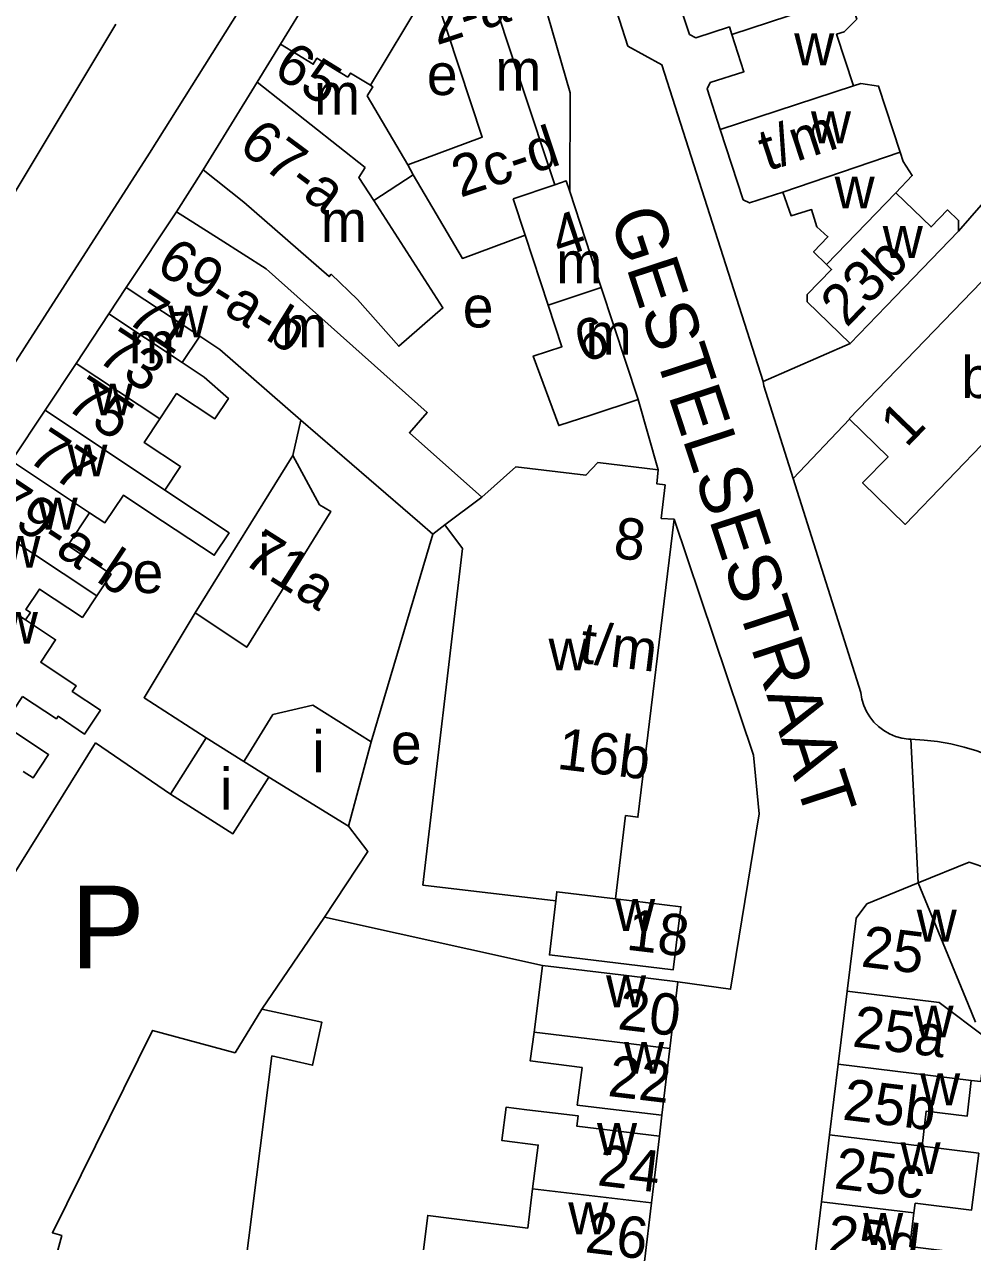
# Model space of a CAD drawing. Extents: x 159700 to 161346, y 381730 to 382922.
# Drawn here: x 160837.1 to 160928.7, y 382582.1 to 382699.7 of the extents above; entities that cross this region are included whole.
import ezdxf

# ---------------------------------------------------------------- set-up
doc = ezdxf.new("R2010")
doc.units = 0
for name, color, linetype in [('BLT_Basislijn', 7, 'Continuous'), ('BLT_Bebouwing', 7, 'Continuous'), ('BLT_Centroide', 7, 'Continuous'), ('BLT_Huisnummer', 7, 'Continuous'), ('BLT_Huisnummer_ tussenligend', 7, 'Continuous'), ('BLT_Huisnummer_reeks', 7, 'Continuous'), ('BLT_Onderdoorgang_en_onderverdeling', 7, 'Continuous'), ('BLT_Onderverdeling_panden', 7, 'Continuous'), ('BLT_Straatnaam', 7, 'Continuous'), ('BLT_Tekst_parkeren', 7, 'Continuous'), ('BLT_Vlakafsluiter', 7, 'Continuous')]:
    doc.layers.add(name, color=color, linetype=linetype)

msp = doc.modelspace()

# ---------------------------------------------------------------- linework, layer by layer
at = {"layer": 'BLT_Basislijn'}
for p, q in [((160854.35, 382685.66), (160851.76, 382681.61)), ((160916.88, 382668.89), (160908.48, 382665.22)), ((160908.48, 382665.22), (160908.53, 382664.81)), ((160908.53, 382664.81), (160911.37, 382655.83)), ((160863.02, 382658.08), (160863.78, 382661.49)), ((160916.8, 382661.59), (160911.37, 382655.83)), ((160911.37, 382655.83), (160917.91, 382635.15)), ((160870.58, 382630.4), (160876.54, 382650.47)), ((160832.19, 382611.45), (160843.92, 382630.3)), ((160843.92, 382630.3), (160851.18, 382625.33)), ((160858.26, 382628.5), (160858.48, 382628.86)), ((160866.07, 382613.44), (160860.02, 382604.55)), ((160887.13, 382608.77), (160866.07, 382613.44)), ((160898.44, 382592.3), (160898.68, 382594.31))]:
    msp.add_line(p, q, dxfattribs=at)
for points in [[(160908.48, 382665.22), (160898.67, 382695.83), (160895.37, 382697.63), (160884.95, 382730.18)], [(160869.96, 382717.52), (160865.52, 382713.53), (160860.57, 382705.45), (160849.16, 382687.27)], [(160885.08, 382709.55), (160889.8, 382693.12), (160889.77, 382683.58)], [(160849.16, 382687.27), (160822.99, 382646.61), (160791.29, 382599.29)], [(160937.77, 382688.16), (160933.93, 382687.28), (160927.35, 382679.74)], [(160896.37, 382663.48), (160898.33, 382656.68)], [(160899.85, 382651.91), (160907.53, 382629.1), (160908.07, 382623.44), (160905.31, 382606.48), (160900.23, 382607.21)], [(160917.91, 382635.15), (160918.01, 382634.53), (160918.19, 382633.92), (160918.45, 382633.34), (160918.78, 382632.8), (160919.17, 382632.3), (160919.62, 382631.86), (160920.13, 382631.48), (160920.68, 382631.16), (160921.26, 382630.92), (160921.88, 382630.74), (160922.5, 382630.65), (160922.73, 382630.64)], [(160922.73, 382630.64), (160924.03, 382630.57), (160925.33, 382630.42), (160926.61, 382630.2), (160927.88, 382629.89), (160929.13, 382629.51), (160930.35, 382629.05), (160931.54, 382628.51), (160932.7, 382627.91), (160933.82, 382627.24), (160934.89, 382626.49), (160935.92, 382625.69), (160936.89, 382624.82), (160937.81, 382623.89), (160938.67, 382622.91), (160939.06, 382622.43)], [(160866.07, 382613.44), (160870.25, 382619.8), (160868.39, 382622.25)]]:
    msp.add_lwpolyline(points, dxfattribs=at)
at = {"layer": 'BLT_Bebouwing'}
for p, q in [((160867.49, 382707.07), (160861.82, 382697.83)), ((160870.51, 382693.84), (160875.99, 382703.02)), ((160861.82, 382697.83), (160859.55, 382694.14)), ((160859.55, 382694.14), (160854.35, 382685.66)), ((160874.11, 382686.15), (160870.2, 382692.84)), ((160870.83, 382682.7), (160874.64, 382685.19)), ((160889.77, 382683.58), (160892.82, 382674.3)), ((160851.76, 382681.61), (160846.91, 382674.29)), ((160916.79, 382661.6), (160930.49, 382675.81)), ((160846.91, 382674.29), (160845.22, 382671.75)), ((160896.37, 382663.48), (160892.82, 382674.3)), ((160845.22, 382671.75), (160842.06, 382666.97)), ((160854, 382669.6), (160852.31, 382667.05)), ((160842.06, 382666.97), (160839.07, 382662.45)), ((160839.07, 382662.45), (160835.81, 382657.54)), ((160875.29, 382651.56), (160863.78, 382661.49)), ((160916.8, 382661.59), (160916.79, 382661.6)), ((160853.56, 382642.87), (160863.02, 382658.08)), ((160854.64, 382630.79), (160851.18, 382625.34)), ((160854.64, 382630.79), (160858.26, 382628.5)), ((160868.39, 382622.25), (160870.58, 382630.4)), ((160868.39, 382622.25), (160860.7, 382626.99)), ((160875.57, 382616.54), (160888.41, 382615.03)), ((160900.23, 382607.21), (160899.46, 382600.76)), ((160915.73, 382599.25), (160916.59, 382606.29)), ((160899.46, 382600.76), (160898.68, 382594.31)), ((160860.97, 382600.04), (160854.79, 382550.82)), ((160914.89, 382592.4), (160915.73, 382599.25)), ((160898.44, 382592.3), (160897.67, 382585.83)), ((160914.11, 382585.95), (160914.89, 382592.4)), ((160913.33, 382579.57), (160914.11, 382585.95))]:
    msp.add_line(p, q, dxfattribs=at)
for points in [[(160881.77, 382704.04), (160877.02, 382702.47), (160876.83, 382702.41), (160881.32, 382688.83), (160874.11, 382686.15)], [(160888.32, 382684.22), (160881.77, 382704.04)], [(160905.43, 382698.76), (160905.2, 382699.48), (160901.95, 382698.43), (160901.33, 382698.76), (160899.49, 382704.43)], [(160914.6, 382701.76), (160915.32, 382701.99), (160917.02, 382701.77), (160917.52, 382700.22), (160916.29, 382699), (160915.57, 382698.77), (160917.19, 382693.78)], [(160904.32, 382689.58), (160903.04, 382693.49), (160903.35, 382694.11), (160906.6, 382695.16), (160905.43, 382698.76)], [(160870.2, 382692.84), (160870.73, 382693.71), (160870.51, 382693.84)], [(160917.19, 382693.78), (160917.92, 382694.01), (160919.62, 382693.77), (160921.71, 382687.37)], [(160910.38, 382683.53), (160907.16, 382682.47), (160906.52, 382682.79), (160904.32, 382689.58)], [(160921.71, 382687.37), (160922, 382686.49), (160922.88, 382685.11), (160921.28, 382683.45)], [(160854.35, 382685.66), (160858.26, 382682.54), (160866.52, 382675.36), (160866.72, 382675.58), (160869.27, 382673.14), (160873.24, 382668.63), (160877.51, 382672.33), (160870.83, 382682.7)], [(160870.83, 382682.7), (160869.39, 382684.94), (160869.98, 382685.9)], [(160874.64, 382685.19), (160879.4, 382677.11), (160885.45, 382679.36)], [(160889.77, 382683.58), (160889.44, 382684.6), (160888.32, 382684.22)], [(160914.59, 382676.52), (160913.34, 382677.74), (160914.73, 382679.2), (160913.66, 382680.15), (160913.14, 382681.83), (160911.16, 382681.24), (160910.38, 382683.53)], [(160921.28, 382683.45), (160924.7, 382680.15), (160926.3, 382681.8), (160927.35, 382680.79), (160927.35, 382679.74)], [(160881.26, 382654.03), (160874.27, 382660.27), (160876, 382662.21), (160860.42, 382676.1), (160855.97, 382678.93), (160851.76, 382681.61)], [(160885.45, 382679.36), (160887.68, 382672.61)], [(160927.35, 382679.74), (160920.36, 382672.49), (160916.88, 382668.89)], [(160916.88, 382668.89), (160912.73, 382672.92), (160912.72, 382673.62), (160915.08, 382676.05), (160914.59, 382676.52)], [(160887.68, 382672.61), (160889.01, 382668.58), (160886.24, 382667.67), (160888.71, 382660.95), (160891.81, 382661.98), (160896.37, 382663.48)], [(160863.78, 382661.49), (160855.96, 382668.3), (160854, 382669.6)], [(160852.31, 382667.05), (160854.42, 382665.65), (160856.78, 382663.58), (160855.47, 382661.61), (160851.77, 382664.05), (160850.16, 382661.61)], [(160935.79, 382662.8), (160931.73, 382658.6), (160930.38, 382659.9), (160922.18, 382651.41), (160918.08, 382655.41), (160920.54, 382657.93), (160916.8, 382661.59)], [(160850.16, 382661.61), (160848.64, 382659.32), (160852.15, 382657), (160850.63, 382654.7)], [(160863.02, 382658.08), (160865.57, 382653.31), (160866.68, 382652.64), (160858.55, 382639.54), (160853.56, 382642.87)], [(160898.33, 382656.68), (160892.48, 382657.38), (160891.34, 382656.16), (160884.57, 382656.98), (160881.26, 382654.03)], [(160898.33, 382656.68), (160898.18, 382655.34), (160899.01, 382655.23)], [(160850.63, 382654.7), (160856.84, 382650.58), (160855.41, 382648.42), (160849.19, 382652.54), (160846.63, 382654.23), (160844.84, 382651.56), (160843.36, 382652.54)], [(160899.01, 382655.23), (160898.62, 382651.98), (160899.85, 382651.91)], [(160843.36, 382652.54), (160841.26, 382649.37), (160845.44, 382646.6), (160844.06, 382644.51)], [(160894.19, 382615.22), (160895.16, 382623.26), (160896.36, 382623.11), (160899.85, 382651.91)], [(160875.29, 382651.56), (160876.54, 382650.47), (160877.71, 382651.35)], [(160877.71, 382651.35), (160879.42, 382649.08), (160875.57, 382616.54)], [(160844.06, 382644.51), (160842.67, 382642.42), (160838.52, 382645.16), (160837.2, 382643.17), (160837.64, 382642.88), (160837.17, 382642.18)], [(160853.56, 382642.87), (160848.62, 382634.65), (160854.64, 382630.79)], [(160837.17, 382642.18), (160840.07, 382640.26), (160838.63, 382638.08), (160842.06, 382635.81), (160841.69, 382635.27), (160844.41, 382633.46), (160842.88, 382631.15), (160840.31, 382632.86), (160840.15, 382632.62), (160836.87, 382634.76)], [(160836.87, 382634.76), (160835.06, 382632.03), (160839.39, 382629.16), (160837.89, 382626.9), (160836.93, 382627.53)], [(160858.48, 382628.86), (160861.08, 382633.03), (160864.95, 382633.93), (160870.58, 382630.4)], [(160851.18, 382625.33), (160857.22, 382621.51), (160860.7, 382626.99)], [(160923.44, 382616.76), (160928.39, 382618.77), (160930.29, 382618.11), (160937.19, 382610.03)], [(160916.59, 382606.29), (160917.45, 382613.36), (160918.49, 382614.75), (160923.44, 382616.76)], [(160894.19, 382615.22), (160900.52, 382614.46), (160899.78, 382608.36), (160887.8, 382609.8), (160888.41, 382615.03)], [(160887.13, 382608.77), (160886.67, 382605.15), (160886.32, 382602.33)], [(160900.23, 382607.21), (160895.26, 382607.8), (160887.13, 382608.77)], [(160841.73, 382579.06), (160839.99, 382580.2), (160840.67, 382582.69), (160839.76, 382582.95), (160849.45, 382602.5), (160857.43, 382600.35), (160860.02, 382604.55)], [(160860.02, 382604.55), (160865.82, 382603.29), (160864.92, 382599.14), (160860.97, 382600.04)], [(160886.32, 382602.33), (160885.96, 382599.56), (160890.96, 382598.92), (160890.5, 382595.29), (160893.72, 382594.9), (160898.68, 382594.31)], [(160928.58, 382597.68), (160929.5, 382597.57), (160930.03, 382601.8)], [(160923.83, 382591.31), (160924.21, 382594.69), (160928.2, 382594.22), (160928.58, 382597.68)], [(160898.44, 382592.3), (160890.47, 382593.25), (160890.59, 382594.24), (160885.62, 382594.84), (160883.61, 382595.08), (160883.21, 382591.86), (160886.72, 382591.42), (160886.18, 382587.2)], [(160923.04, 382584.86), (160923.16, 382585.8), (160928.62, 382585.14), (160929.31, 382590.64), (160923.83, 382591.31)], [(160880.34, 382580.41), (160875.6, 382581.03), (160876.05, 382584.63), (160885.71, 382583.41), (160886.18, 382587.2)], [(160897.67, 382585.83), (160896.99, 382580.17), (160896.76, 382578.41)], [(160927.71, 382577.82), (160928.09, 382580.94), (160922.65, 382581.61), (160923.04, 382584.86)]]:
    msp.add_lwpolyline(points, dxfattribs=at)
at = {"layer": 'BLT_Onderdoorgang_en_onderverdeling'}
for p, q in [((160846.91, 382674.29), (160854, 382669.6)), ((160845.22, 382671.75), (160852.31, 382667.05))]:
    msp.add_line(p, q, dxfattribs=at)
at = {"layer": 'BLT_Onderverdeling_panden'}
for p, q in [((160914.6, 382701.76), (160905.43, 382698.76)), ((160869.98, 382685.9), (160859.55, 382694.14)), ((160917.19, 382693.78), (160904.32, 382689.58)), ((160910.38, 382683.53), (160921.71, 382687.37)), ((160874.11, 382686.15), (160874.64, 382685.19)), ((160884.29, 382682.88), (160888.32, 382684.22)), ((160885.45, 382679.36), (160884.29, 382682.88)), ((160921.28, 382683.45), (160914.59, 382676.52)), ((160887.68, 382672.61), (160892.82, 382674.3)), ((160850.16, 382661.61), (160842.06, 382666.97)), ((160850.63, 382654.7), (160839.07, 382662.45)), ((160843.36, 382652.54), (160835.81, 382657.54)), ((160877.71, 382651.35), (160881.26, 382654.03)), ((160844.06, 382644.51), (160832.33, 382652.28)), ((160837.17, 382642.18), (160829.16, 382647.49)), ((160858.26, 382628.5), (160860.7, 382626.99)), ((160923.44, 382616.76), (160928.28, 382605.04)), ((160928.28, 382605.04), (160929, 382603.3)), ((160899.46, 382600.76), (160886.32, 382602.33)), ((160928.58, 382597.68), (160915.73, 382599.25)), ((160923.83, 382591.31), (160914.89, 382592.4)), ((160886.18, 382587.2), (160897.67, 382585.83)), ((160923.04, 382584.86), (160914.11, 382585.95))]:
    msp.add_line(p, q, dxfattribs=at)
for points in [[(160868.33, 382694.63), (160865.34, 382696.46), (160864.98, 382695.88), (160861.82, 382697.83)], [(160868.33, 382694.63), (160868.58, 382695.03), (160870.51, 382693.84)], [(160888.41, 382615.03), (160888.51, 382615.9), (160894.19, 382615.22)], [(160930.03, 382601.8), (160925.49, 382605.21), (160916.59, 382606.29)]]:
    msp.add_lwpolyline(points, dxfattribs=at)
at = {"layer": 'BLT_Vlakafsluiter'}
for p, q in [((160845.88, 382699.75), (160835.86, 382683.08)), ((160923.44, 382616.76), (160922.73, 382630.64))]:
    msp.add_line(p, q, dxfattribs=at)

# ---------------------------------------------------------------- texts
at = {"layer": 'BLT_Centroide'}
for s, p in [('w', (160911.47, 382695.78)), ('e', (160875.96, 382692.9)), ('m', (160882.58, 382693.31)), ('m', (160865.05, 382690.99)), ('w', (160913.09, 382688.25)), ('w', (160915.38, 382681.94)), ('m', (160865.7, 382678.71)), ('w', (160920.03, 382677.16)), ('m', (160888.46, 382674.72)), ('e', (160879.43, 382670.44)), ('w', (160850.93, 382669.47)), ('m', (160861.87, 382668.53)), ('m', (160891.3, 382667.81)), ('m', (160847.16, 382666.97)), ('b', (160927.63, 382663.62)), ('w', (160843.67, 382661.95)), ('w', (160841.22, 382656.05)), ('w', (160838.34, 382650.91)), ('i', (160859.66, 382646.5)), ('w', (160834.75, 382647.22)), ('e', (160847.51, 382644.77)), ('w', (160834.5, 382639.88)), ('w', (160887.72, 382637.3)), ('i', (160864.89, 382627.46)), ('e', (160872.48, 382628.21)), ('i', (160855.97, 382623.85)), ('w', (160894.16, 382612.12)), ('w', (160923.31, 382611.09)), ('w', (160893.28, 382604.75)), ('w', (160923.01, 382601.84)), ('w', (160895.02, 382598.31)), ('w', (160923.64, 382595.28)), ('w', (160892.41, 382590.47)), ('w', (160921.75, 382588.62)), ('w', (160889.63, 382582.81)), ('w', (160918.13, 382581.78))]:
    msp.add_text(s, height=4, dxfattribs=at).set_placement(p)
at = {"layer": 'BLT_Huisnummer'}
for s, rotation, p in [('65', 328.2919, (160860.95, 382694.88)), ('4', 18.2676, (160888.79, 382677.13)), ('6', 18.265, (160891.06, 382666.99)), ('73', 326.4875, (160843.91, 382667.3)), ('1', 45.9711, (160922.3, 382658.74)), ('77', 326.4943, (160837.19, 382657.63)), ('71a', 327.6061, (160857.99, 382647.76)), ('18', 353.1708, (160895.14, 382610.32)), ('25', 353.0448, (160917.84, 382608.69)), ('20', 353.165, (160894.31, 382602.64)), ('25a', 353.0487, (160917, 382600.96)), ('24', 353.1725, (160892.35, 382587.55)), ('25c', 353.0454, (160915.24, 382587.26))]:
    msp.add_text(s, height=4, rotation=rotation, dxfattribs=at).set_placement(p)
at = {"layer": 'BLT_Huisnummer_ tussenligend'}
for s, rotation, p in [('71', 326.479, (160846.74, 382671.05)), ('75', 326.4913, (160840.89, 382662.67)), ('22', 353.165, (160893.36, 382596.18)), ('25b', 353.0435, (160916.05, 382593.9)), ('26', 353.1725, (160891.15, 382581.08)), ('25d', 353.0458, (160914.48, 382580.75))]:
    msp.add_text(s, height=4, rotation=rotation, dxfattribs=at).set_placement(p)
at = {"layer": 'BLT_Huisnummer_reeks'}
for s, rotation, p in [('2-a-b', 18.3094, (160876.92, 382697.69)), ('67-a', 323.3991, (160857.61, 382687.65)), ('2c-d', 18.3045, (160879.19, 382682.97)), ('t/m', 18.0658, (160908.85, 382685.53)), ('69-a-b', 328.2919, (160849.61, 382675.93)), ('23b', 46.0213, (160916.54, 382670.35)), ('79-a-b', 326.4816, (160833.48, 382652.87)), ('8', 353.2055, (160893.89, 382648.19)), ('t/m', 353.0855, (160890.61, 382638.05)), ('16b', 353.1077, (160888.44, 382627.8))]:
    msp.add_text(s, height=4, rotation=rotation, dxfattribs=at).set_placement(p)
at = {"layer": 'BLT_Straatnaam'}
msp.add_text('GESTELSESTRAAT', height=5, rotation=288.1609, dxfattribs=at).set_placement((160893.59, 382681.2))
at = {"layer": 'BLT_Tekst_parkeren'}
msp.add_text('P', height=8, dxfattribs=at).set_placement((160841.54, 382608.49))

doc.saveas('drawing.dxf')
